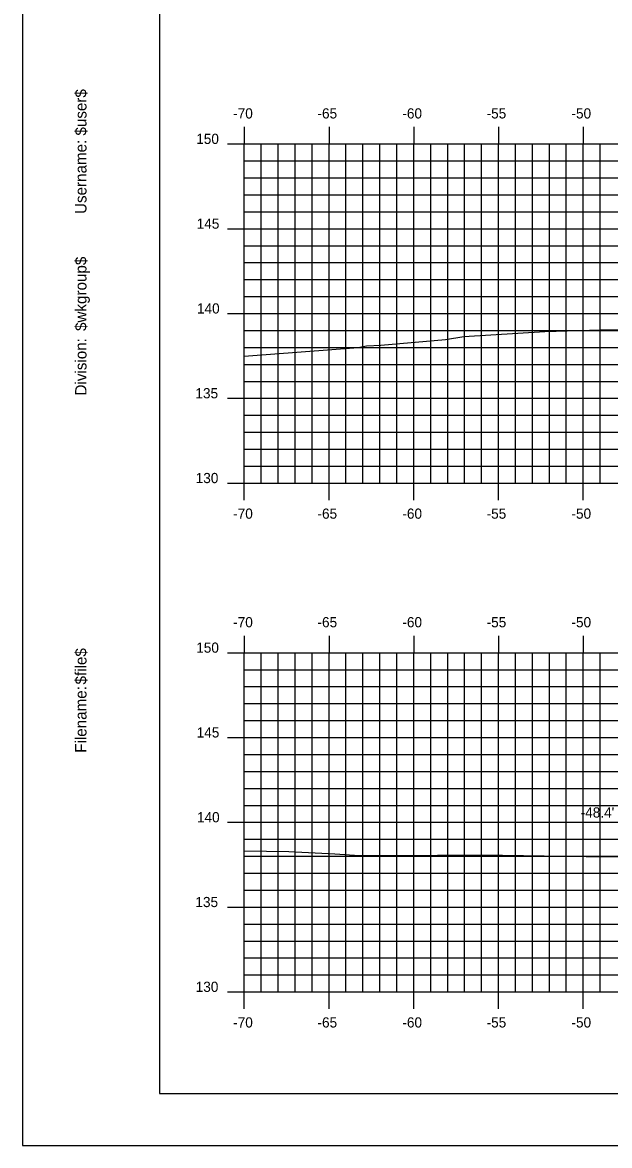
# Model space of a CAD drawing. Extents: x 851417 to 851588, y 365876 to 365986.
# Drawn here: x 851416.8 to 851451.5, y 365875.8 to 365942 of the extents above; entities that cross this region are included whole.
import ezdxf

# ---------------------------------------------------------------- set-up
doc = ezdxf.new("R2010")
doc.units = 0
for name, color, linetype in [('BORDER', 7, 'Continuous'), ('D_Text_Standard', 7, 'Continuous'), ('H_V ANNOTATION', 7, 'Continuous'), ('MAJOR', 7, 'Continuous'), ('MINOR', 7, 'Continuous'), ('PLOT BOUNDARY', 7, 'Continuous'), ('S_Roadway_Centerline', 7, 'Continuous')]:
    doc.layers.add(name, color=color, linetype=linetype)

msp = doc.modelspace()

# ---------------------------------------------------------------- linework, layer by layer
at = {"layer": 'BORDER'}
msp.add_lwpolyline([(851424.899, 365878.833), (851584.899, 365878.833), (851584.899, 365983.833), (851424.899, 365983.833)], close=True, dxfattribs=at)
at = {"layer": 'MAJOR'}
for p, q in [((851429.898, 365935.835), (851429.898, 365934.833)), ((851434.898, 365935.835), (851434.898, 365934.833)), ((851439.898, 365935.835), (851439.898, 365934.833)), ((851444.898, 365935.835), (851444.898, 365934.833)), ((851449.898, 365935.835), (851449.898, 365934.833)), ((851428.896, 365934.833), (851429.898, 365934.833)), ((851429.898, 365934.833), (851569.898, 365934.833)), ((851429.898, 365914.833), (851429.898, 365934.833)), ((851429.898, 365914.833), (851429.898, 365934.833)), ((851429.898, 365934.833), (851569.898, 365934.833)), ((851434.898, 365914.833), (851434.898, 365934.833)), ((851439.898, 365914.833), (851439.898, 365934.833)), ((851444.898, 365914.833), (851444.898, 365934.833)), ((851449.898, 365914.833), (851449.898, 365934.833)), ((851428.896, 365929.833), (851429.898, 365929.833)), ((851429.898, 365929.833), (851569.898, 365929.833)), ((851428.896, 365924.833), (851429.898, 365924.833)), ((851429.898, 365924.833), (851569.898, 365924.833)), ((851428.896, 365919.833), (851429.898, 365919.833)), ((851429.898, 365919.833), (851569.898, 365919.833)), ((851428.896, 365914.833), (851429.898, 365914.833)), ((851429.898, 365914.833), (851569.898, 365914.833)), ((851429.898, 365914.833), (851569.898, 365914.833)), ((851429.898, 365913.831), (851429.898, 365914.833)), ((851434.898, 365913.831), (851434.898, 365914.833)), ((851439.898, 365913.831), (851439.898, 365914.833)), ((851444.898, 365913.831), (851444.898, 365914.833)), ((851449.898, 365913.831), (851449.898, 365914.833)), ((851429.898, 365905.835), (851429.898, 365904.833)), ((851434.898, 365905.835), (851434.898, 365904.833)), ((851439.898, 365905.835), (851439.898, 365904.833)), ((851444.898, 365905.835), (851444.898, 365904.833)), ((851449.898, 365905.835), (851449.898, 365904.833)), ((851428.896, 365904.833), (851429.898, 365904.833)), ((851429.898, 365904.833), (851569.898, 365904.833)), ((851429.898, 365884.833), (851429.898, 365904.833)), ((851429.898, 365884.833), (851429.898, 365904.833)), ((851429.898, 365904.833), (851569.898, 365904.833)), ((851434.898, 365884.833), (851434.898, 365904.833)), ((851439.898, 365884.833), (851439.898, 365904.833)), ((851444.898, 365884.833), (851444.898, 365904.833)), ((851449.898, 365884.833), (851449.898, 365904.833)), ((851428.896, 365899.833), (851429.898, 365899.833)), ((851429.898, 365899.833), (851569.898, 365899.833)), ((851428.896, 365894.833), (851429.898, 365894.833)), ((851429.898, 365894.833), (851569.898, 365894.833)), ((851428.896, 365889.833), (851429.898, 365889.833)), ((851429.898, 365889.833), (851569.898, 365889.833)), ((851428.896, 365884.833), (851429.898, 365884.833)), ((851429.898, 365884.833), (851569.898, 365884.833)), ((851429.898, 365884.833), (851569.898, 365884.833)), ((851429.898, 365883.831), (851429.898, 365884.833)), ((851434.898, 365883.831), (851434.898, 365884.833)), ((851439.898, 365883.831), (851439.898, 365884.833)), ((851444.898, 365883.831), (851444.898, 365884.833)), ((851449.898, 365883.831), (851449.898, 365884.833))]:
    msp.add_line(p, q, dxfattribs=at)
at = {"layer": 'MINOR'}
for p, q in [((851430.898, 365914.833), (851430.898, 365934.833)), ((851431.898, 365914.833), (851431.898, 365934.833)), ((851432.898, 365914.833), (851432.898, 365934.833)), ((851433.898, 365914.833), (851433.898, 365934.833)), ((851435.898, 365914.833), (851435.898, 365934.833)), ((851436.898, 365914.833), (851436.898, 365934.833)), ((851437.898, 365914.833), (851437.898, 365934.833)), ((851438.898, 365914.833), (851438.898, 365934.833)), ((851440.898, 365914.833), (851440.898, 365934.833)), ((851441.898, 365914.833), (851441.898, 365934.833)), ((851442.898, 365914.833), (851442.898, 365934.833)), ((851443.898, 365914.833), (851443.898, 365934.833)), ((851445.898, 365914.833), (851445.898, 365934.833)), ((851446.898, 365914.833), (851446.898, 365934.833)), ((851447.898, 365914.833), (851447.898, 365934.833)), ((851448.898, 365914.833), (851448.898, 365934.833)), ((851450.898, 365914.833), (851450.898, 365934.833)), ((851429.898, 365933.833), (851569.898, 365933.833)), ((851429.898, 365933.833), (851430.9, 365933.833)), ((851429.898, 365932.833), (851569.898, 365932.833)), ((851429.898, 365932.833), (851430.9, 365932.833)), ((851429.898, 365931.833), (851569.898, 365931.833)), ((851429.898, 365931.833), (851430.9, 365931.833)), ((851429.898, 365930.833), (851569.898, 365930.833)), ((851429.898, 365930.833), (851430.9, 365930.833)), ((851429.898, 365928.833), (851569.898, 365928.833)), ((851429.898, 365928.833), (851430.9, 365928.833)), ((851429.898, 365927.833), (851569.898, 365927.833)), ((851429.898, 365927.833), (851430.9, 365927.833)), ((851429.898, 365926.833), (851569.898, 365926.833)), ((851429.898, 365926.833), (851430.9, 365926.833)), ((851429.898, 365925.833), (851569.898, 365925.833)), ((851429.898, 365925.833), (851430.9, 365925.833)), ((851429.898, 365923.833), (851569.898, 365923.833)), ((851429.898, 365923.833), (851430.9, 365923.833)), ((851429.898, 365922.833), (851569.898, 365922.833)), ((851429.898, 365922.833), (851430.9, 365922.833)), ((851429.898, 365921.833), (851569.898, 365921.833)), ((851429.898, 365921.833), (851430.9, 365921.833)), ((851429.898, 365920.833), (851569.898, 365920.833)), ((851429.898, 365920.833), (851430.9, 365920.833)), ((851429.898, 365918.833), (851569.898, 365918.833)), ((851429.898, 365918.833), (851430.9, 365918.833)), ((851429.898, 365917.833), (851569.898, 365917.833)), ((851429.898, 365917.833), (851430.9, 365917.833)), ((851429.898, 365916.833), (851569.898, 365916.833)), ((851429.898, 365916.833), (851430.9, 365916.833)), ((851429.898, 365915.833), (851569.898, 365915.833)), ((851429.898, 365915.833), (851430.9, 365915.833)), ((851430.898, 365884.833), (851430.898, 365904.833)), ((851431.898, 365884.833), (851431.898, 365904.833)), ((851432.898, 365884.833), (851432.898, 365904.833)), ((851433.898, 365884.833), (851433.898, 365904.833)), ((851435.898, 365884.833), (851435.898, 365904.833)), ((851436.898, 365884.833), (851436.898, 365904.833)), ((851437.898, 365884.833), (851437.898, 365904.833)), ((851438.898, 365884.833), (851438.898, 365904.833)), ((851440.898, 365884.833), (851440.898, 365904.833)), ((851441.898, 365884.833), (851441.898, 365904.833)), ((851442.898, 365884.833), (851442.898, 365904.833)), ((851443.898, 365884.833), (851443.898, 365904.833)), ((851445.898, 365884.833), (851445.898, 365904.833)), ((851446.898, 365884.833), (851446.898, 365904.833)), ((851447.898, 365884.833), (851447.898, 365904.833)), ((851448.898, 365884.833), (851448.898, 365904.833)), ((851450.898, 365884.833), (851450.898, 365904.833)), ((851429.898, 365903.833), (851569.898, 365903.833)), ((851429.898, 365903.833), (851430.9, 365903.833)), ((851429.898, 365902.833), (851569.898, 365902.833)), ((851429.898, 365902.833), (851430.9, 365902.833)), ((851429.898, 365901.833), (851569.898, 365901.833)), ((851429.898, 365901.833), (851430.9, 365901.833)), ((851429.898, 365900.833), (851569.898, 365900.833)), ((851429.898, 365900.833), (851430.9, 365900.833)), ((851429.898, 365898.833), (851569.898, 365898.833)), ((851429.898, 365898.833), (851430.9, 365898.833)), ((851429.898, 365897.833), (851569.898, 365897.833)), ((851429.898, 365897.833), (851430.9, 365897.833)), ((851429.898, 365896.833), (851569.898, 365896.833)), ((851429.898, 365896.833), (851430.9, 365896.833)), ((851429.898, 365895.833), (851569.898, 365895.833)), ((851429.898, 365895.833), (851430.9, 365895.833)), ((851429.898, 365893.833), (851569.898, 365893.833)), ((851429.898, 365893.833), (851430.9, 365893.833)), ((851429.898, 365892.833), (851569.898, 365892.833)), ((851429.898, 365892.833), (851430.9, 365892.833)), ((851429.898, 365891.833), (851569.898, 365891.833)), ((851429.898, 365891.833), (851430.9, 365891.833)), ((851429.898, 365890.833), (851569.898, 365890.833)), ((851429.898, 365890.833), (851430.9, 365890.833)), ((851429.898, 365888.833), (851569.898, 365888.833)), ((851429.898, 365888.833), (851430.9, 365888.833)), ((851429.898, 365887.833), (851569.898, 365887.833)), ((851429.898, 365887.833), (851430.9, 365887.833)), ((851429.898, 365886.833), (851569.898, 365886.833)), ((851429.898, 365886.833), (851430.9, 365886.833)), ((851429.898, 365885.833), (851569.898, 365885.833)), ((851429.898, 365885.833), (851430.9, 365885.833))]:
    msp.add_line(p, q, dxfattribs=at)
at = {"layer": 'PLOT BOUNDARY'}
msp.add_lwpolyline([(851416.805, 365875.774), (851586.805, 365875.774), (851586.805, 365985.774), (851416.805, 365985.774)], close=True, dxfattribs=at)
at = {"layer": 'S_Roadway_Centerline'}
for points in [[(851429.898, 365922.321), (851436.61, 365922.828), (851437.101, 365922.924), (851437.946, 365922.975), (851441.767, 365923.308), (851442.861, 365923.48), (851447.638, 365923.77), (851450.942, 365923.866), (851452.19, 365923.878)], [(851429.898, 365893.146), (851432.516, 365893.121), (851435.234, 365892.968), (851436.694, 365892.871), (851438.683, 365892.869), (851443.9, 365892.913), (851450.071, 365892.818), (851455.254, 365892.773)]]:
    msp.add_lwpolyline(points, dxfattribs=at)

# ---------------------------------------------------------------- texts
at = {"layer": 'BORDER'}
for s, p in [('$user$', (851420.584, 365935.325)), ('Username:', (851420.584, 365930.701)), ('$wkgroup$', (851420.584, 365923.803)), ('Division:', (851420.584, 365919.999)), ('$file$', (851420.584, 365902.959)), ('Filename:', (851420.584, 365898.932))]:
    msp.add_text(s, height=0.6696, rotation=90, dxfattribs=at).set_placement(p)
at = {"layer": 'D_Text_Standard'}
msp.add_text("-48.4'", height=0.6, dxfattribs=at).set_placement((851449.747, 365895.114))
at = {"layer": 'H_V ANNOTATION'}
for s, p in [('-70', (851429.24, 365936.333)), ('-65', (851434.216, 365936.333)), ('-60', (851439.224, 365936.333)), ('-55', (851444.195, 365936.333)), ('-50', (851449.203, 365936.333)), ('150', (851427.06, 365934.833)), ('145', (851427.087, 365929.833)), ('140', (851427.103, 365924.833)), ('135', (851427.012, 365919.833)), ('130', (851427.028, 365914.833)), ('-70', (851429.24, 365912.733)), ('-65', (851434.216, 365912.733)), ('-60', (851439.224, 365912.733)), ('-55', (851444.195, 365912.733)), ('-50', (851449.203, 365912.733)), ('-70', (851429.24, 365906.333)), ('-65', (851434.216, 365906.333)), ('-60', (851439.224, 365906.333)), ('-55', (851444.195, 365906.333)), ('-50', (851449.203, 365906.333)), ('150', (851427.06, 365904.833)), ('145', (851427.087, 365899.833)), ('140', (851427.103, 365894.833)), ('135', (851427.012, 365889.833)), ('130', (851427.028, 365884.833)), ('-70', (851429.24, 365882.733)), ('-65', (851434.216, 365882.733)), ('-60', (851439.224, 365882.733)), ('-55', (851444.195, 365882.733)), ('-50', (851449.203, 365882.733))]:
    msp.add_text(s, height=0.6, dxfattribs=at).set_placement(p)
at = {"layer": 'MAJOR'}
for p in [(851429.894, 365914.833), (851429.894, 365884.833)]:
    msp.add_text('-', height=0.006, dxfattribs=at).set_placement(p)

doc.saveas('drawing.dxf')
